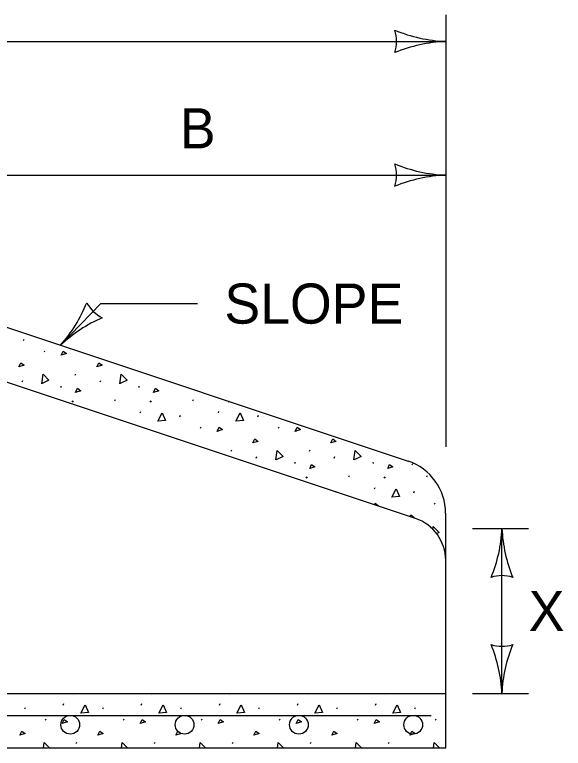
# Model space of a CAD drawing. Extents: x 49991.4 to 50022.1, y 49985 to 50011.4.
# Drawn here: x 50010.964 to 50011.784, y 49995.4 to 49996.497 of the extents above; entities that cross this region are included whole.
import ezdxf

# ---------------------------------------------------------------- set-up
doc = ezdxf.new("R2010")
doc.units = 0
for name, color, linetype in [('Level 1', 7, 'Continuous'), ('Level 2', 7, 'Continuous'), ('Level 3', 7, 'Continuous')]:
    doc.layers.add(name, color=color, linetype=linetype)

msp = doc.modelspace()

# ---------------------------------------------------------------- linework, layer by layer
at = {"layer": 'Level 1'}
for p, q in [((50010.8686, 49996.0573), (50011.5522, 49995.8295)), ((50010.9772, 49996.0097), (50010.9782, 49996.0119)), ((50011.0077, 49995.9941), (50011.0087, 49995.9927)), ((50011.5634, 49995.7435), (50010.8686, 49995.975)), ((50011.0545, 49995.9578), (50011.0554, 49995.96)), ((50010.9748, 49995.9479), (50010.9758, 49995.95)), ((50011.0915, 49995.9479), (50011.0925, 49995.95)), ((50011.0327, 49995.9417), (50011.033, 49995.9395)), ((50011.1494, 49995.9417), (50011.1497, 49995.9395)), ((50011.1137, 49995.9196), (50011.1146, 49995.9218)), ((50011.2303, 49995.9196), (50011.2313, 49995.9218)), ((50011.0493, 49995.9196), (50011.0503, 49995.9181)), ((50011.0503, 49995.919), (50011.0513, 49995.9176)), ((50011.166, 49995.9196), (50011.167, 49995.9181)), ((50011.167, 49995.919), (50011.168, 49995.9176)), ((50011.283, 49995.9192), (50011.2837, 49995.9181)), ((50011.2837, 49995.919), (50011.2847, 49995.9176)), ((50011.1517, 49995.9015), (50011.1526, 49995.9037)), ((50011.2684, 49995.9015), (50011.2693, 49995.9037)), ((50011.2106, 49995.8959), (50011.2116, 49995.8981)), ((50011.3273, 49995.8959), (50011.3283, 49995.8981)), ((50011.2411, 49995.8804), (50011.242, 49995.8789)), ((50011.3578, 49995.8804), (50011.3587, 49995.8789)), ((50011.2878, 49995.8441), (50011.2888, 49995.8462)), ((50011.4045, 49995.8441), (50011.4055, 49995.8462)), ((50011.3249, 49995.8341), (50011.3258, 49995.8363)), ((50011.4416, 49995.8341), (50011.4425, 49995.8363)), ((50011.3828, 49995.8279), (50011.383, 49995.8258)), ((50011.4995, 49995.8279), (50011.4997, 49995.8258)), ((50011.5584, 49995.8241), (50011.5591, 49995.8257)), ((50011.3994, 49995.8058), (50011.4004, 49995.8043)), ((50011.4004, 49995.8053), (50011.4014, 49995.8038)), ((50011.4637, 49995.8058), (50011.4647, 49995.808)), ((50011.5161, 49995.8058), (50011.5171, 49995.8043)), ((50011.5171, 49995.8053), (50011.5181, 49995.8038)), ((50011.5804, 49995.8058), (50011.5814, 49995.808)), ((50011.5017, 49995.7878), (50011.5027, 49995.7899)), ((50011.4445, 49995.7831), (50011.445, 49995.7843)), ((50011.5607, 49995.7821), (50011.5617, 49995.7843)), ((50011.5911, 49995.7666), (50011.5921, 49995.7651)), ((50011.6084, 49995.3998), (50011.6084, 49995.7515)), ((50009.6906, 49995.4819), (50011.6084, 49995.4819)), ((50011.0514, 49995.4819), (50011.0519, 49995.4811)), ((50011.0519, 49995.482), (50011.0528, 49995.4806)), ((50011.168, 49995.4819), (50011.1685, 49995.4811)), ((50011.1685, 49995.482), (50011.1695, 49995.4806)), ((50011.2847, 49995.4819), (50011.2852, 49995.4811)), ((50011.2852, 49995.482), (50011.2862, 49995.4806)), ((50011.4014, 49995.4819), (50011.4019, 49995.4811)), ((50011.4019, 49995.482), (50011.4029, 49995.4806)), ((50011.5181, 49995.4819), (50011.5186, 49995.4811)), ((50011.5186, 49995.482), (50011.5196, 49995.4806)), ((50010.9788, 49995.4589), (50010.9798, 49995.4611)), ((50011.0365, 49995.4645), (50011.0375, 49995.4667)), ((50011.0955, 49995.4589), (50011.0964, 49995.4611)), ((50011.1532, 49995.4645), (50011.1542, 49995.4667)), ((50011.2122, 49995.4589), (50011.2131, 49995.4611)), ((50011.2699, 49995.4645), (50011.2709, 49995.4667)), ((50011.3288, 49995.4589), (50011.3298, 49995.4611)), ((50011.3866, 49995.4645), (50011.3876, 49995.4667)), ((50011.4455, 49995.4589), (50011.4465, 49995.4611)), ((50011.5033, 49995.4645), (50011.5042, 49995.4667)), ((50011.5622, 49995.4589), (50011.5632, 49995.4611)), ((50011.0092, 49995.4434), (50011.0102, 49995.4419)), ((50011.1259, 49995.4434), (50011.1269, 49995.4419)), ((50011.2426, 49995.4434), (50011.2436, 49995.4419)), ((50011.3593, 49995.4434), (50011.3603, 49995.4419)), ((50011.476, 49995.4434), (50011.477, 49995.4419)), ((50011.5927, 49995.4434), (50011.5936, 49995.4419)), ((50011.056, 49995.4071), (50011.057, 49995.4092)), ((50011.1727, 49995.4071), (50011.1737, 49995.4092)), ((50011.2894, 49995.4071), (50011.2904, 49995.4092)), ((50011.4061, 49995.4071), (50011.407, 49995.4092)), ((50011.5228, 49995.4071), (50011.5237, 49995.4092)), ((50011.6084, 49995.3998), (50009.6084, 49995.3998))]:
    msp.add_line(p, q, dxfattribs=at)
for points in [[(50011.0333, 49995.9878), (50011.0362, 49995.9939), (50011.0411, 49995.9902), (50011.0333, 49995.9878)], [(50010.97, 49995.9704), (50010.9729, 49995.9765), (50010.9778, 49995.9728), (50010.97, 49995.9704)], [(50011.0867, 49995.9704), (50011.0896, 49995.9765), (50011.0945, 49995.9728), (50011.0867, 49995.9704)], [(50011.0044, 49995.9453), (50011.0064, 49995.9593), (50011.0151, 49995.9503), (50011.0047, 49995.9454)], [(50011.1211, 49995.9453), (50011.1231, 49995.9593), (50011.1318, 49995.9503), (50011.1214, 49995.9454)], [(50011.055, 49995.9323), (50011.0579, 49995.9384), (50011.0627, 49995.9347), (50011.055, 49995.9323)], [(50011.1716, 49995.9323), (50011.1746, 49995.9384), (50011.1794, 49995.9347), (50011.1716, 49995.9323)], [(50011.1777, 49995.8894), (50011.1843, 49995.9018), (50011.1894, 49995.8903), (50011.178, 49995.8894)], [(50011.2944, 49995.8894), (50011.301, 49995.9018), (50011.3061, 49995.8903), (50011.2947, 49995.8894)], [(50011.2666, 49995.874), (50011.2696, 49995.8801), (50011.2744, 49995.8765), (50011.2666, 49995.874)], [(50011.3833, 49995.874), (50011.3863, 49995.8801), (50011.3911, 49995.8765), (50011.3833, 49995.874)], [(50011.2062, 49995.8625), (50011.2063, 49995.8627), (50011.2068, 49995.8623)], [(50011.32, 49995.8566), (50011.323, 49995.8627), (50011.3278, 49995.859), (50011.32, 49995.8566)], [(50011.4367, 49995.8566), (50011.4397, 49995.8627), (50011.4445, 49995.859), (50011.4367, 49995.8566)], [(50011.3545, 49995.8315), (50011.3564, 49995.8455), (50011.3652, 49995.8365), (50011.3547, 49995.8316)], [(50011.4712, 49995.8315), (50011.4731, 49995.8455), (50011.4819, 49995.8365), (50011.4714, 49995.8316)], [(50011.405, 49995.8185), (50011.4079, 49995.8246), (50011.4128, 49995.8209), (50011.405, 49995.8185)], [(50011.5217, 49995.8185), (50011.5246, 49995.8246), (50011.5295, 49995.8209), (50011.5217, 49995.8185)], [(50011.5278, 49995.7756), (50011.5344, 49995.788), (50011.5395, 49995.7765), (50011.528, 49995.7756)], [(50011.5018, 49995.764), (50011.5029, 49995.7663), (50011.5078, 49995.7627), (50011.5068, 49995.7624)], [(50011.5551, 49995.7463), (50011.5563, 49995.7489), (50011.5612, 49995.7452), (50011.5597, 49995.7447)], [(50011.5892, 49995.7271), (50011.5898, 49995.7317), (50011.5985, 49995.7227), (50011.594, 49995.7206)], [(50011.0626, 49995.4524), (50011.0692, 49995.4648), (50011.0743, 49995.4533), (50011.0628, 49995.4524)], [(50011.1793, 49995.4524), (50011.1858, 49995.4648), (50011.191, 49995.4533), (50011.1795, 49995.4524)], [(50011.296, 49995.4524), (50011.3025, 49995.4648), (50011.3077, 49995.4533), (50011.2962, 49995.4524)], [(50011.4126, 49995.4524), (50011.4192, 49995.4648), (50011.4243, 49995.4533), (50011.4129, 49995.4524)], [(50011.5293, 49995.4524), (50011.5359, 49995.4648), (50011.541, 49995.4533), (50011.5296, 49995.4524)], [(50009.706, 49995.4491), (50011.5866, 49995.4491)], [(50011.0348, 49995.437), (50011.0377, 49995.4431), (50011.0426, 49995.4395), (50011.0348, 49995.437)], [(50011.1515, 49995.437), (50011.1544, 49995.4431), (50011.1593, 49995.4395), (50011.1515, 49995.437)], [(50011.2682, 49995.437), (50011.2711, 49995.4431), (50011.276, 49995.4395), (50011.2682, 49995.437)], [(50011.3849, 49995.437), (50011.3878, 49995.4431), (50011.3927, 49995.4395), (50011.3849, 49995.437)], [(50011.5016, 49995.437), (50011.5045, 49995.4431), (50011.5094, 49995.4395), (50011.5016, 49995.437)], [(50010.9715, 49995.4196), (50010.9744, 49995.4257), (50010.9793, 49995.422), (50010.9715, 49995.4196)], [(50011.0882, 49995.4196), (50011.0911, 49995.4257), (50011.096, 49995.422), (50011.0882, 49995.4196)], [(50011.2049, 49995.4196), (50011.2078, 49995.4257), (50011.2127, 49995.422), (50011.2049, 49995.4196)], [(50011.3216, 49995.4196), (50011.3245, 49995.4257), (50011.3294, 49995.422), (50011.3216, 49995.4196)], [(50011.4383, 49995.4196), (50011.4412, 49995.4257), (50011.4461, 49995.422), (50011.4383, 49995.4196)], [(50011.555, 49995.4196), (50011.5579, 49995.4257), (50011.5628, 49995.422), (50011.555, 49995.4196)], [(50011.0067, 49995.3998), (50011.0079, 49995.4085), (50011.0163, 49995.3998)], [(50011.1234, 49995.3998), (50011.1246, 49995.4085), (50011.133, 49995.3998)], [(50011.2401, 49995.3998), (50011.2413, 49995.4085), (50011.2497, 49995.3998)], [(50011.3568, 49995.3998), (50011.358, 49995.4085), (50011.3664, 49995.3998)], [(50011.4735, 49995.3998), (50011.4747, 49995.4085), (50011.4831, 49995.3998)], [(50011.5902, 49995.3998), (50011.5914, 49995.4085), (50011.5998, 49995.3998)]]:
    msp.add_lwpolyline(points, dxfattribs=at)
for centre in [(50011.0469, 49995.4351), (50011.2179, 49995.4351), (50011.3888, 49995.4351), (50011.5598, 49995.4351)]:
    msp.add_circle(centre, 0.014, dxfattribs=at)
for centre, radius, end in [((50011.5261, 49995.7515), 0.0822, 71.5597), ((50011.5426, 49995.6811), 0.0658, 71.5569)]:
    msp.add_arc(centre, radius, 0, end, dxfattribs=at)
at = {"layer": 'Level 3'}
for p, q in [((50011.6084, 49996.4973), (50011.6084, 49995.9869)), ((50009.6084, 49996.4573), (50011.6084, 49996.4573)), ((50010.8686, 49996.2573), (50011.6084, 49996.2573)), ((50011.0927, 49996.0651), (50011.0324, 49996.0027)), ((50011.0927, 49996.0651), (50011.2374, 49996.0651)), ((50011.6084, 49995.9869), (50011.6084, 49995.8508)), ((50011.6484, 49995.7286), (50011.7325, 49995.7286)), ((50011.6925, 49995.4819), (50011.6925, 49995.7286)), ((50011.6484, 49995.4819), (50011.7325, 49995.4819))]:
    msp.add_line(p, q, dxfattribs=at)
for centre, radius, start, end in [((50011.6176, 49996.6794), 0.2223, 247.456, 267.6395), ((50011.4802, 49996.4573), 0.0548, 342.1388, 17.8612), ((50011.6199, 49996.2246), 0.233, 92.8273, 112.0772), ((50011.6176, 49996.4794), 0.2223, 247.456, 267.6395), ((50011.4802, 49996.2573), 0.0548, 342.1388, 17.8612), ((50011.6199, 49996.0246), 0.233, 92.8273, 112.0772), ((50010.8642, 49996.1501), 0.2237, 318.7754, 338.0252), ((50011.118, 49996.0912), 0.0526, 208.0869, 243.8093), ((50011.1796, 49995.8481), 0.2134, 113.4041, 133.5876), ((50011.4793, 49995.7374), 0.2134, 337.456, 357.6395), ((50011.9159, 49995.7396), 0.2237, 182.8273, 202.0772), ((50011.6925, 49995.6055), 0.0526, 72.1388, 107.8612), ((50011.6925, 49995.605), 0.0526, 252.1388, 287.8612), ((50011.4691, 49995.4709), 0.2237, 2.8273, 22.0772), ((50011.9057, 49995.4731), 0.2134, 157.456, 177.6395)]:
    msp.add_arc(centre, radius, start, end, dxfattribs=at)

# ---------------------------------------------------------------- texts
at = {"layer": 'Level 2'}
for s, p in [('B', (50011.2108, 49996.2973)), ('SLOPE', (50011.2774, 49996.0351)), ('X', (50011.7325, 49995.5753))]:
    msp.add_text(s, height=0.06, dxfattribs=at).set_placement(p)

doc.saveas('drawing.dxf')
